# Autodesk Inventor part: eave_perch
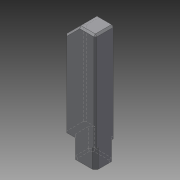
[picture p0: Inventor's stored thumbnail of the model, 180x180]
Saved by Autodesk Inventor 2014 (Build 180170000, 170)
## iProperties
Created: 2013-07
Part Number: eave_perch
Material: Generic
Document SubType Name: Modeling
Designer: Brent J. Rosenburgh
Density: 1 g/cm^3
Appearance: Default
Author: Brent J. Rosenburgh
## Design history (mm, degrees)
sketch "Sketch1"
  geometry: L1 (-2.531, 2.995)-(2.533, 2.995); L2 (3.533, 1.995)-(3.533, -1.953); L3 (2.533, -2.953)-(-2.531, -2.953); L4 (-3.531, -1.953)-(-3.531, 1.995); L5 (-2.531, 2.995)-(-3.531, 1.995); L6 (2.533, 2.995)-(3.533, 1.995); L7 (3.533, -1.953)-(2.533, -2.953); L8 (-2.531, -2.953)-(-3.531, -1.953); 1 further point
  constraints: 16 end point, 2 parallel, 1 horizontal, 1 perpendicular
extrude "Extrusion1" new body sketch "Sketch1" distance "d0" = 6.25; taper "d1" = 0 deg
chamfer "Chamfer1" distance "d2" = 0.5; stored, may be unused: second distance "d3" = 2, angle "d4" = 45 deg
sketch "Sketch2"
  geometry: L1 (2.533, 2.995)-(-2.531, 2.995) reference; L2 (3.533, 2.995)-(-5.671, 2.995); L3 (-5.671, 2.995)-(-5.671, -2.953); L4 (-5.671, -2.953)-(3.533, -2.953); L5 (3.533, -2.953)-(3.533, 2.995); 1 further point
  constraints: 8 end point, 2 parallel, 1 horizontal, 1 perpendicular, 1 point on line
extrude "Extrusion2" join sketch "Sketch2" distance "d5" = 30; taper "d6" = 0 deg
chamfer "Chamfer2" distance "d7" = 4.25; stored, may be unused: second distance "d8" = 2, angle "d9" = 45 deg
chamfer "Chamfer3" distance "d10" = 0.5; stored, may be unused: second distance "d11" = 2, angle "d12" = 45 deg
body "Solid1"
